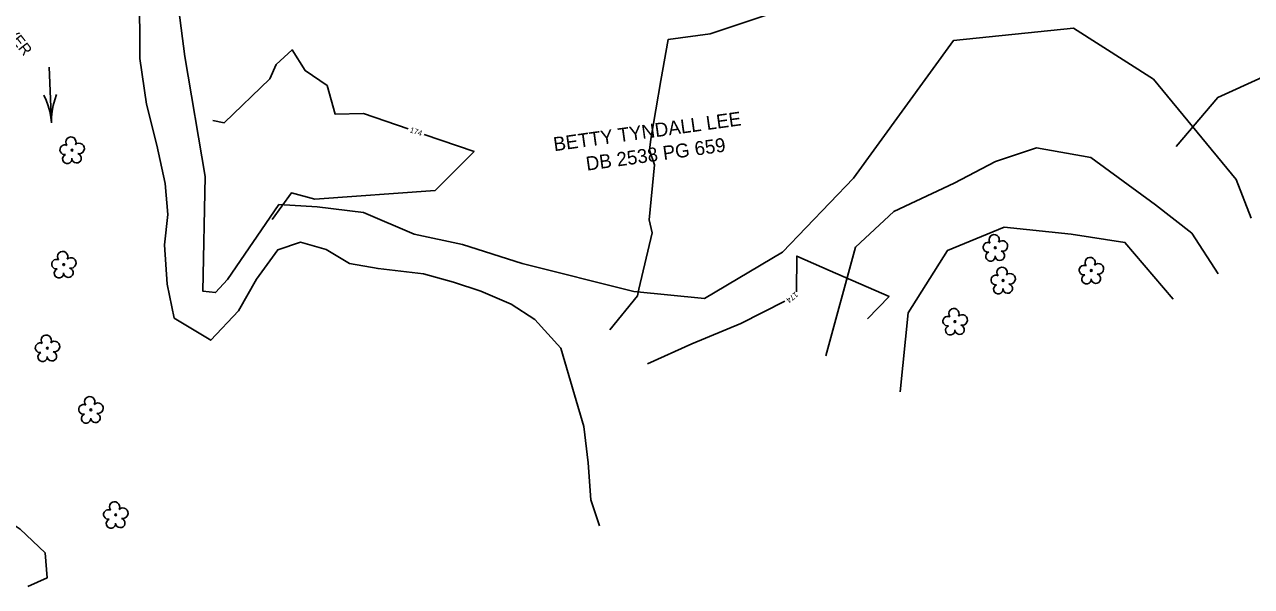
# Model space of a CAD drawing. Extents: x 2086416 to 2115205, y 575507 to 632762.
# Drawn here: x 2112066 to 2112506.7, y 581424.6 to 581626.3 of the extents above; entities that cross this region are included whole.
import ezdxf

# ---------------------------------------------------------------- set-up
doc = ezdxf.new("R2010")
doc.units = 0
for name, color, linetype in [('DTM Contours Minor', 7, 'Continuous'), ('DTM Contours Minor Text', 7, 'Continuous'), ('Exist Hydro River Flow Arrow CELL', 7, 'Continuous'), ('Exist Hydro Stream or Body of Water', 7, 'Continuous'), ('Exist Hydro Stream or Body of Water Text', 7, 'Continuous'), ('Exist Property Deed Book Text', 7, 'Continuous'), ('Exist Property Owner Text', 7, 'Continuous'), ('Exist Vegetation Tree CELL', 7, 'Continuous'), ('Exist Vegetation Woods Line', 7, 'Continuous')]:
    doc.layers.add(name, color=color, linetype=linetype)

# ---------------------------------------------------------------- blocks, each defined once
blk = doc.blocks.new('EXIST VEGETATION TREE')
at = {"layer": 'Exist Vegetation Tree CELL'}
blk.add_line((0, 0), (0, 0), dxfattribs=at)
blk.add_circle((0, 0), 0.00652, dxfattribs=at)
for centre, radius, start, end in [((-0.0077, 0.0575), 0.0371, 330.16508, 219.71335), ((-0.0521, 0.0031), 0.0345, 62.66361, 279.3457), ((0.051, 0.0118), 0.038, 257.1011, 134.19993), ((-0.0341, -0.0624), 0.0338, 111.56708, 6.23104), ((0.0335, -0.058), 0.034, 181.28216, 74.55999)]:
    blk.add_arc(centre, radius, start, end, dxfattribs=at)

msp = doc.modelspace()

# ---------------------------------------------------------------- linework, layer by layer
at = {"layer": 'DTM Contours Minor'}
for points in [[(2112479.65, 581582.55), (2112494.63, 581600.06), (2112510.74, 581607.39), (2112511.06, 581608.94), (2112512.53, 581609.55), (2112516.2, 581625.91), (2112517.14, 581631.82), (2112515.63, 581637.39), (2112510.62, 581636.54), (2112490.05, 581656.84), (2112487.22, 581660.78), (2112464.7, 581658.06), (2112464.67, 581680.55), (2112462.55, 581681.73), (2112449.73, 581694.94), (2112449.13, 581696.4), (2112446.55, 581697.34), (2112441.2, 581700.56), (2112438.42, 581700.91), (2112433.07, 581701.29), (2112430.5, 581702.23), (2112429.31, 581702.63)], [(2112337.5, 581644.27), (2112336.58, 581635.42), (2112335.7, 581630.66), (2112312.26, 581622.94), (2112297.16, 581620.89), (2112294.63, 581606.21), (2112290.94, 581585.17), (2112290.56, 581581.19), (2112292.27, 581575.91), (2112290.35, 581556.21), (2112291.44, 581551.51), (2112286.69, 581531.27), (2112286.24, 581528.95), (2112276.21, 581516.73)], [(2112203.87, 581588.83), (2112187.77, 581594.37), (2112177.63, 581594.06), (2112174.78, 581604.36), (2112166.82, 581609.74), (2112162.13, 581617.23), (2112156.43, 581611.99), (2112154.08, 581606.82), (2112137.78, 581591.03), (2112133.7, 581591.82)], [(2112155.02, 581556.29), (2112161.87, 581565.86), (2112170.31, 581563.58), (2112213.47, 581566.73), (2112227.5, 581580.69), (2112209.54, 581586.87)], [(2112368.77, 581520.65), (2112376.54, 581528.63), (2112355.38, 581537.89), (2112343.38, 581543.19), (2112343.32, 581530.34)], [(2112339.06, 581526.96), (2112323.28, 581518.99), (2112305.68, 581511.73), (2112289.76, 581504.5)]]:
    msp.add_lwpolyline(points, dxfattribs=at)
at = {"layer": 'Exist Hydro River Flow Arrow CELL'}
for p, q in [((2112075.67, 581591.04), (2112074.89, 581611.02)), ((2112072.99, 581600.94), (2112073.85, 581599.09)), ((2112073.85, 581599.09), (2112074.57, 581597.14)), ((2112075.28, 581601.03), (2112075.28, 581601.03)), ((2112076.85, 581599.2), (2112076.29, 581597.2)), ((2112077.56, 581601.12), (2112076.85, 581599.2)), ((2112074.57, 581597.14), (2112075.12, 581595.12)), ((2112075.12, 581595.12), (2112075.52, 581593.08)), ((2112075.9, 581595.15), (2112075.67, 581593.09)), ((2112076.29, 581597.2), (2112075.9, 581595.15)), ((2112075.52, 581593.08), (2112075.67, 581591.04)), ((2112075.67, 581593.09), (2112075.67, 581591.04))]:
    msp.add_line(p, q, dxfattribs=at)
at = {"layer": 'Exist Hydro Stream or Body of Water'}
for points in [[(2112107.33, 581639.18), (2112107.41, 581614.06), (2112109.89, 581597.75), (2112113.53, 581583.01), (2112116.51, 581569.23), (2112117.49, 581558.07), (2112116.35, 581547.27), (2112117.29, 581533.07), (2112119.76, 581520.96), (2112132.9, 581512.98), (2112142.84, 581523.55), (2112149.34, 581534.91), (2112156.95, 581545.38), (2112165.09, 581548.19), (2112174.41, 581545.52), (2112182.72, 581540.54), (2112193, 581538.7), (2112209.38, 581536.76), (2112220.15, 581533.84), (2112229.97, 581530.56), (2112240.78, 581525.96), (2112249.31, 581520.47), (2112258.6, 581510.17), (2112263.57, 581493.45), (2112266.97, 581482.01), (2112268.42, 581468.95), (2112269.45, 581455.73), (2112272.6, 581446.43)], [(2112353.85, 581507.34), (2112364.55, 581546.41), (2112378.28, 581559.23), (2112399.98, 581569.33), (2112414.76, 581577.08), (2112429.5, 581582.08), (2112449.06, 581578.51), (2112472.23, 581561.59), (2112485.25, 581551.36), (2112494.82, 581536.85)], [(2112067.22, 581424.64), (2112074.1, 581427.73), (2112073.39, 581436.72), (2112064.5, 581445.16), (2112053.96, 581452.19), (2112024.09, 581474.58), (2112019.7, 581502.3), (2112021.09, 581515.42), (2112020.9, 581535.88), (2112022.05, 581547.38), (2112026.79, 581556.19)], [(2112478.58, 581527.78), (2112461.28, 581548.07), (2112441.91, 581551.09), (2112417.9, 581553.52), (2112397.53, 581545.23), (2112383.47, 581522.77), (2112380.57, 581494.45)]]:
    msp.add_lwpolyline(points, dxfattribs=at)
at = {"layer": 'Exist Vegetation Woods Line'}
for points in [[(2112223.29, 581547.33), (2112206.03, 581551.03), (2112187.8, 581558.85), (2112171.15, 581560.85), (2112157.41, 581561.71), (2112138.87, 581534.84), (2112134.62, 581530.07), (2112130.01, 581530.64), (2112130.9, 581571.76), (2112123.57, 581614.86), (2112118.67, 581652.85), (2112111.96, 581666.92)], [(2112506.64, 581556.81), (2112501.25, 581570.63), (2112471.5, 581606.66), (2112442.86, 581624.99), (2112399.66, 581620.5), (2112363.78, 581571.14), (2112338.31, 581544.6), (2112310.24, 581527.95), (2112284.9, 581530.53), (2112244.71, 581540.51), (2112223.29, 581547.33)]]:
    msp.add_lwpolyline(points, dxfattribs=at)

# ---------------------------------------------------------------- block references
at = {"layer": 'Exist Vegetation Tree CELL', "xscale": 50, "yscale": 50}
for p in [(2112083.07, 581581.2), (2112414.7, 581546.19), (2112080.09, 581540.13), (2112449.18, 581538), (2112417.5, 581534.44), (2112400.23, 581519.66), (2112074.21, 581510.14), (2112089.83, 581488.02), (2112098.75, 581450.33)]:
    msp.add_blockref('EXIST VEGETATION TREE', p, dxfattribs=at)

# ---------------------------------------------------------------- texts
at = {"layer": 'DTM Contours Minor Text'}
for rotation, p in [(340.9909, (2112204.23, 581587.65)), (218.3524, (2112342.9, 581530.51))]:
    msp.add_text('174', height=2, rotation=rotation, dxfattribs=at).set_placement(p)
at = {"layer": 'Exist Hydro Stream or Body of Water Text'}
msp.add_text('BLACK RIVER', height=4, rotation=307.9408, dxfattribs=at).set_placement((2112044.15, 581642.61))
at = {"layer": 'Exist Property Deed Book Text'}
msp.add_text('DB 2538 PG 659', height=5, rotation=7.8831, dxfattribs=at).set_placement((2112268.02, 581573.81))
at = {"layer": 'Exist Property Owner Text'}
msp.add_text('BETTY TYNDALL LEE', height=5, rotation=7.883, dxfattribs=at).set_placement((2112256.34, 581580.8))

doc.saveas('drawing.dxf')
